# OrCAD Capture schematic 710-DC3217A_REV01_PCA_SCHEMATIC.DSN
size B
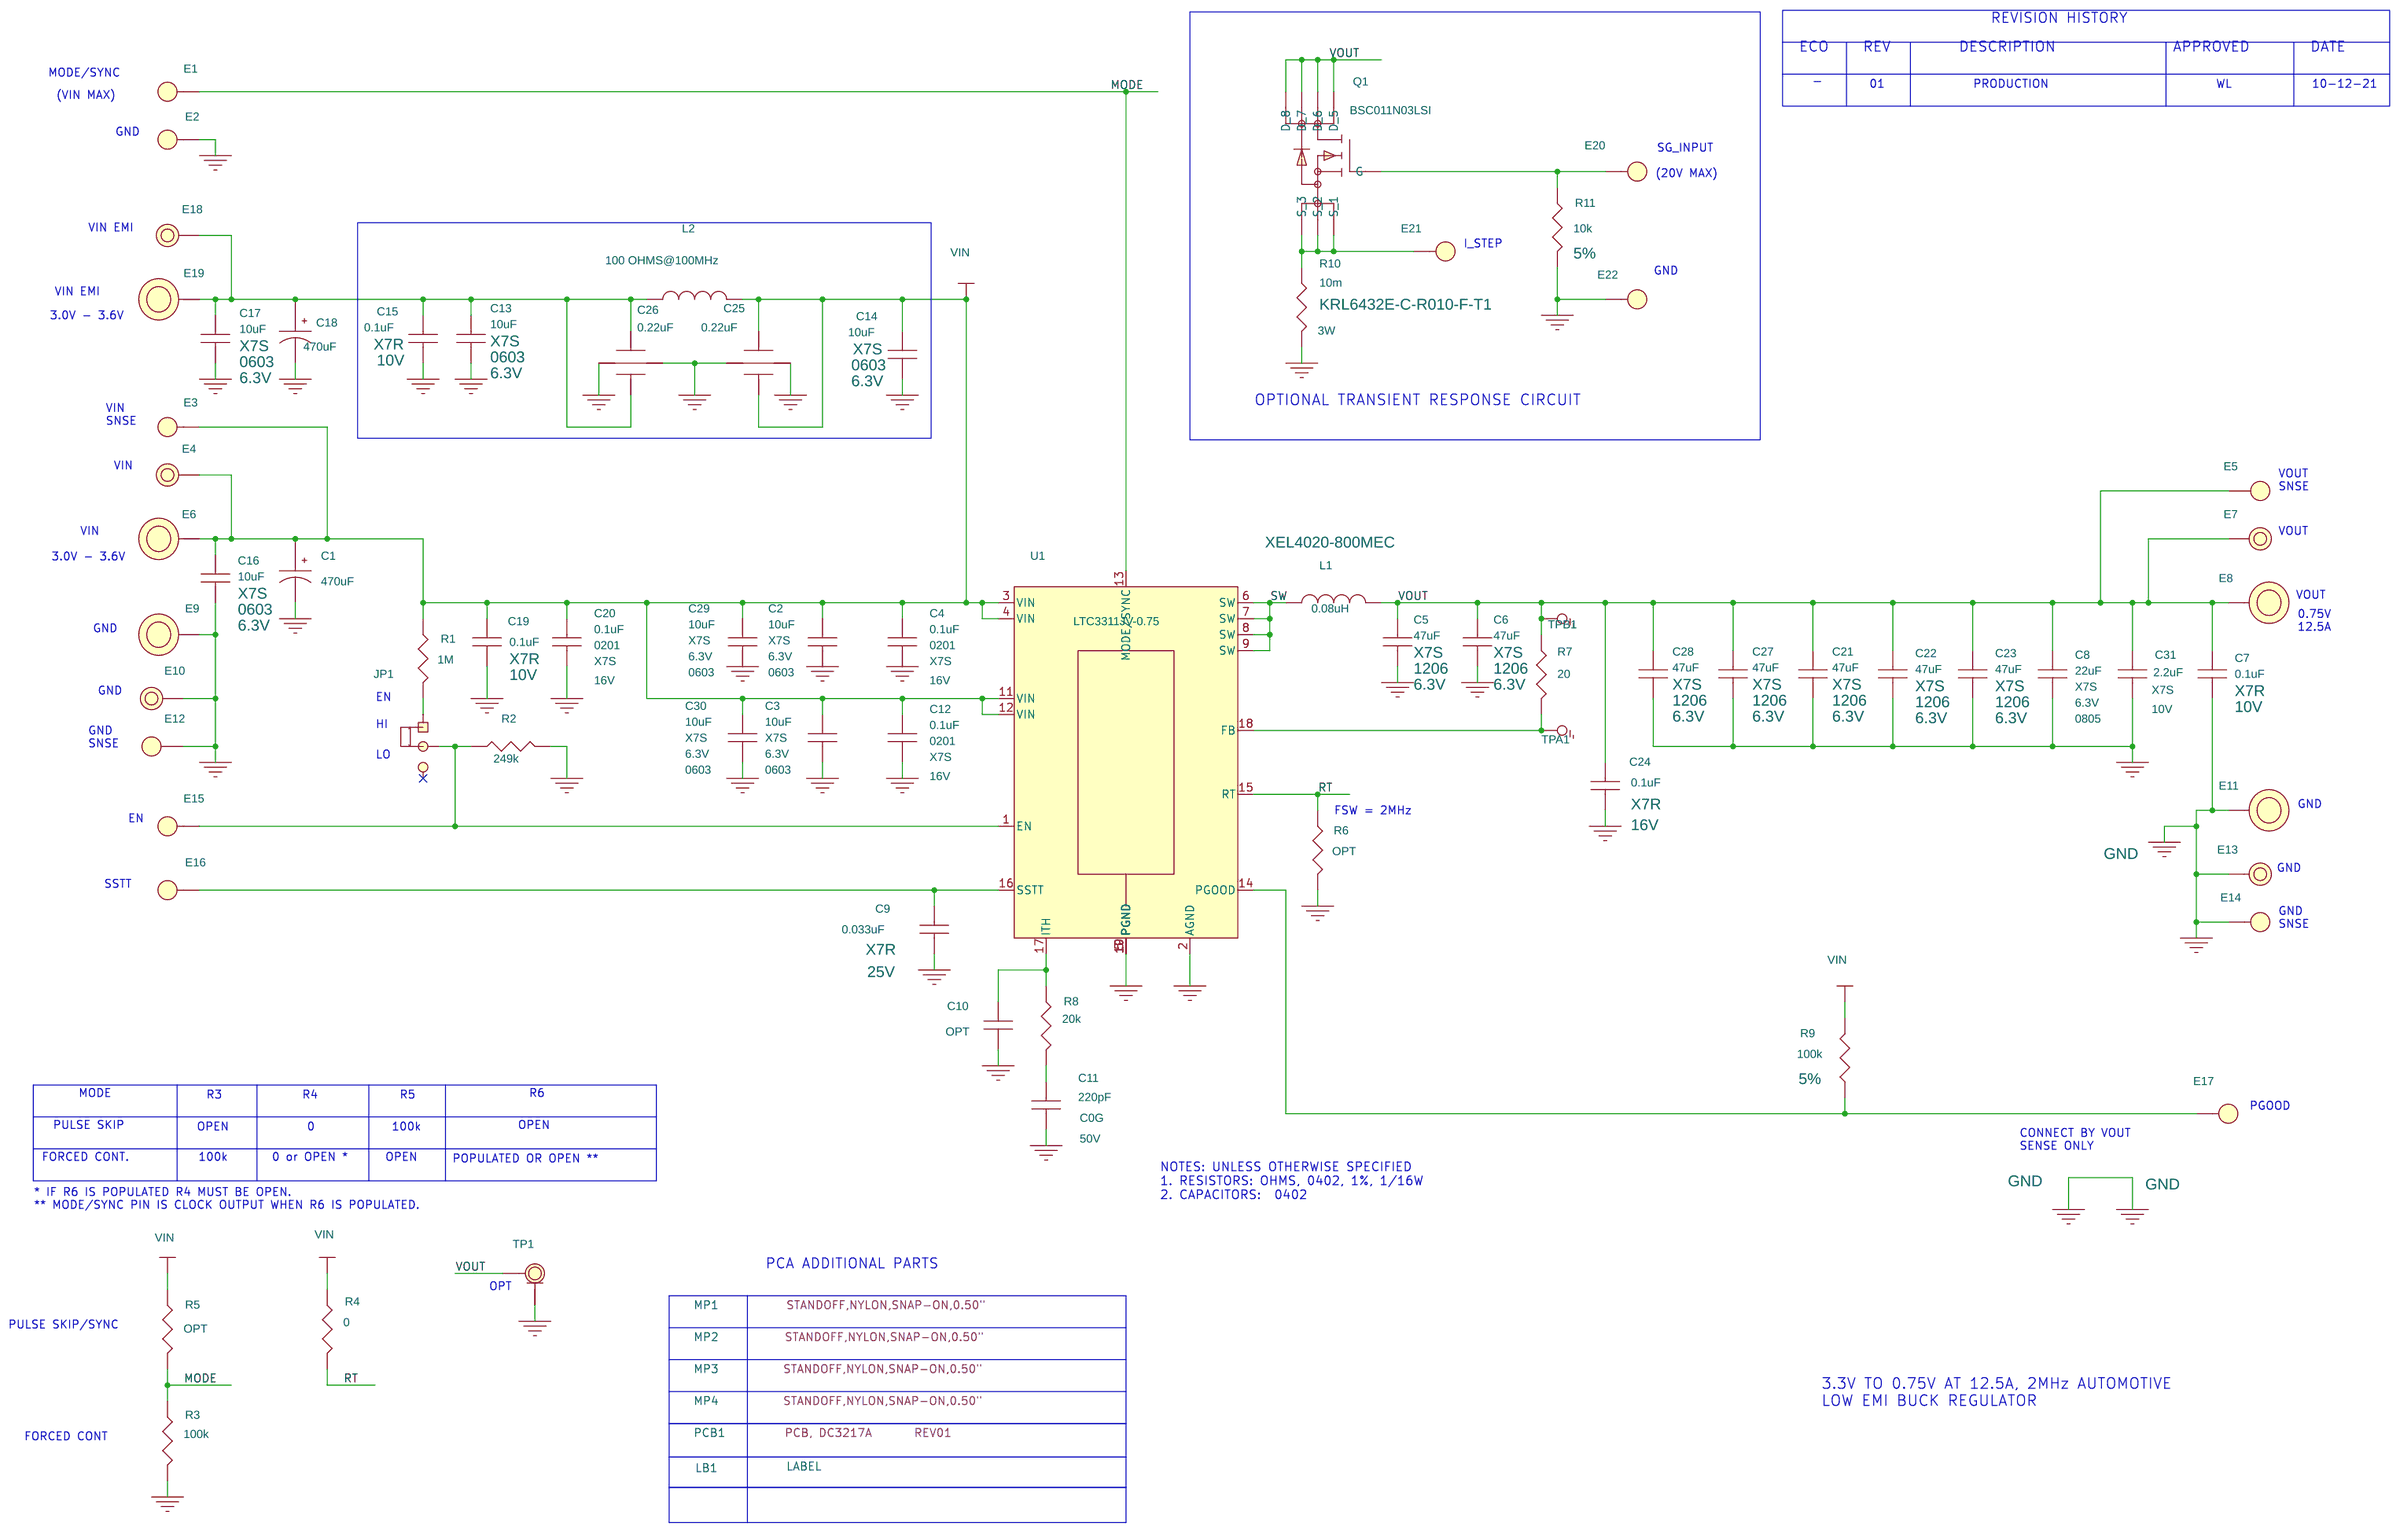
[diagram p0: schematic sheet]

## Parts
C1  470uF  [CAPMP7343N]
C2  10uF  [CC0603N]
C3  10uF  [CC0603N]
C4  0.1uF  [CC0201M]
C5  47uF  [CC1206N]
C6  47uF  [CC1206N]
C7  0.1uF  [CC0402N]
C8  22uF  [CC0805N]
C9  0.033uF  [CC0402N]
C10  OPT  [CC0402N]
C11  220pF  [CC0402N]
C12  0.1uF  [CC0201M]
C13  10uF  [CC0603N]
C14  10uF  [CC0603N]
C15  0.1uF  [CC0402N]
C16  10uF  [CC0603N]
C17  10uF  [CC0603N]
C18  470uF  [CAPMP7343N]
C19  0.1uF  [CC0402N]
C20  0.1uF  [CC0201M]
C21  47uF  [CC1206N]
C22  47uF  [CC1206N]
C23  47uF  [CC1206N]
C24  0.1uF  [CC0402N]
C25  0.22uF  [JOHANSON-X2Y-X14]
C26  0.22uF  [JOHANSON-X2Y-X14]
C27  47uF  [CC1206N]
C28  47uF  [CC1206N]
C29  10uF  [CC0603N]
C30  10uF  [CC0603N]
C31  2.2uF  [CC0402N]
E1  TEST POINT  [MILLMAX2308]
E2  TEST POINT  [MILLMAX2308]
E3  TEST POINT  [MILLMAX2308]
E4  TEST POINT  [MILLMAX2501]
E5  TEST POINT  [MILLMAX2308]
E6  BANANA JACK  [KEY-575-4]
E7  TEST POINT  [MILLMAX2501]
E8  BANANA JACK  [KEY-575-4]
E9  BANANA JACK  [KEY-575-4]
E10  TEST POINT  [MILLMAX2501]
E11  BANANA JACK  [KEY-575-4]
E12  TEST POINT  [MILLMAX2308]
E13  TEST POINT  [MILLMAX2501]
E14  TEST POINT  [MILLMAX2308]
E15  TEST POINT  [MILLMAX2308]
E16  TEST POINT  [MILLMAX2308]
E17  TEST POINT  [MILLMAX2308]
E18  TEST POINT  [MILLMAX2501]
E19  BANANA JACK  [KEY-575-4]
E20  TEST POINT  [MILLMAX2308]
E21  TEST POINT  [MILLMAX2308]
E22  TEST POINT  [MILLMAX2308]
JP1  HDR  [HD1X3-079]
L1  0.08uH  [COILCRAFT-XEL4020]
L2  100 OHMS@100MHz  [WURTH-74279226101]
LB1  LABEL  [895-0154_REV01]
MP1  STANDOFF  [KEYSTONE_8829-8834]
MP2  STANDOFF  [KEYSTONE_8829-8834]
MP3  STANDOFF  [KEYSTONE_8829-8834]
MP4  STANDOFF  [KEYSTONE_8829-8834]
PCB1  PCB, DC3217A
Q1  BSC011N03LSI  [INFINEON-PG-TDSON-8]
R1  1M  [CR0402N]
R2  249k  [CR0402N]
R3  100k  [CR0402N]
R4  0  [CR0402N]
R5  OPT  [CR0402N]
R6  OPT  [CR0402N]
R7  20  [CR0402N]
R8  20k  [CR0402N]
R9  100k  [CR0402N]
R10  10m  [SUSUMU-KRL6432]
R11  10k  [CR0402N]
TP1  U.FL  [HIROSE-FL-R-SMT-1]
TPA1  COPPER FEATURE PAD  [PADSTYLE1]
TPB1  COPPER FEATURE PAD  [PADSTYLE1]
U1  LTC3311JV-0.75  [LTC-LQFN-18-1548]
XJP1  SHUNT  [SAMTEC-SHUNT-079]

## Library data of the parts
C1 C18 = CAP_P_ALT: CAP.,470uF,TANT,POSCAP,6.3V,20%,7343,10mOHMS,TCF; CLASS: DISCRETE; Dielectric Type: TANT,POSCAP; FPLIST: CAPMP7343N,CAPMP7343L,CAPMP7343M; Inventory Qty: 4200; Manufacturer: PANASONIC; Manufacturer PN: 6TCF470MAH; PART_NUMBER: 150-0550; Package Size: 7343; Rated Voltage: 6.3V; Tolerance: 20%
C2 C3 C13 C14 C16 C17 C29 C30 = CAP: CAP.,10uF,X7S,6.3V,20%,0603; CLASS: DISCRETE; Dielectric Type: X7S; FPLIST: CC0603N,CC0603L,CC0603M; Inventory Qty: 34800; Manufacturer: TDK; Manufacturer PN: C1608X7S0J106M080AC; PART_NUMBER: 150-1745; Package Size: 0603; Rated Voltage: 6.3V; Tolerance: 20%
C4 C12 C20 = CAP: CAP.,0.1uF,X7S,16V,10%,0201; CLASS: DISCRETE; Dielectric Type: X7S; FPLIST: CC0201N,CC0201L,CC0201M; Inventory Qty: 73200; Manufacturer: MURATA; Manufacturer PN: GRM033C71C104KE14D; PART_NUMBER: 150-0807; Package Size: 0201; Rated Voltage: 16V; Temperature Coefficient: X7S; Tolerance: 10%
C5 C6 C21-C23 C27 C28 = CAP: CAP.,47uF,X7S,6.3V,20%,1206; CLASS: DISCRETE; Dielectric Type: X7S; FPLIST: CC1206N,CC1206L,CC1206M; Inventory Qty: 7200; Manufacturer: TDK; Manufacturer PN: C3216X7S0J476M160AC; PART_NUMBER: 150-2602; Package Size: 1206; Rated Voltage: 6.3V; Tolerance: 20%
C7 C15 C19 = CAP: CAP.,0.1uF,X7R,10V,10%,0402,AEC-Q200; CLASS: DISCRETE; Dielectric Type: X7R; FPLIST: CC0402N,CC0402L,CC0402M; Inventory Qty: 59100; Manufacturer: MURATA; Manufacturer PN: GCM155R71A104KA55D; PART_NUMBER: 150-1790; Package Size: 0402; Rated Voltage: 10V; Temperature Coefficient: X7R; Tolerance: 10%
C8 = CAP: CAP.,22uF,X7S,6.3V,20%,0805; CLASS: DISCRETE; Dielectric Type: X7S; FPLIST: CC0805N,CC0805L,CC0805M; Inventory Qty: 12300; Manufacturer: TDK; Manufacturer PN: C2012X7S0J226M125AC; PART_NUMBER: 150-0806; Package Size: 0805; Rated Voltage: 6.3V; Temperature Coefficient: X7S; Tolerance: 20%
C9 = CAP: CAP.,0.033uF,X7R,25V,10%,0402; CLASS: DISCRETE; Dielectric Type: X7R; FPLIST: CC0402N,CC0402L,CC0402M; Inventory Qty: 27937; Manufacturer: KEMET; Manufacturer PN: C0402C333K3RACTU; PART_NUMBER: 150-0484; Package Size: 0402; Rated Voltage: 25V; Tolerance: 10%
C10 = CAP: CAP., OPTION, 0402; CLASS: DISCRETE; FPLIST: CC0402N,CC0402L,CC0402M; PART_NUMBER: 150-3148; Package Size: 0402; Package Type: SMD
C11 = CAP: CAP.,220pF,C0G,50V,5%,0402; CLASS: DISCRETE; Dielectric Type: C0G; FPLIST: CC0402N,CC0402L,CC0402M; Inventory Qty: 29935; Manufacturer: AVX; Manufacturer PN: 04025A221JAT2A; PART_NUMBER: 150-2013; Package Size: 0402; Rated Voltage: 50V; Tolerance: 5%
C24 = CAP: CAP.,0.1uF,X7R,16V,10%,0402,AEC-Q200; CLASS: DISCRETE; Dielectric Type: X7R; Inventory Qty: 0; Manufacturer: MURATA; Manufacturer PN: GCM155R71C104KA55D; PART_NUMBER: 150-1882; Package Size: 0402; Package Type: Surface Mount, MLCC; Rated Voltage: 16V; Temperature Coefficient: X7R; Tolerance: 10%
C25 C26 = JOHANSON-X2Y: CAP.,0.22uF,X7R,6.3V,20%,0603; CLASS: DISCRETE; Dielectric Type: X7R; Inventory Qty: 12000; Manufacturer: JOHANSON DIELECTRICS; Manufacturer PN: 6R3X14W224MV4T; PART_NUMBER: 150-0876; Package Size: 0603; Rated Voltage: 6.3V; Temperature Coefficient: X7R; Tolerance: 20%
C31 = CAP: CAP.,2.2uf,X7S,10V,10%,0402,AEC-Q200; CLASS: DISCRETE; Dielectric Type: X7S; FPLIST: CC0402N,CC0402L,CC0402M; Inventory Qty: 0; Manufacturer: MURATA; Manufacturer PN: GRT155C71A225KE13D; PART_NUMBER: 150-1884; Package Size: 0402; Package Type: Surface Mount, MLCC; Rated Voltage: 10V; Temperature Coefficient: X7S; Tolerance: 10%
E1-E3 E5 E12 E14-E17 E20-E22 = TEST_POINT_.156_MILL-MAX_2308: TEST POINT,TURRET,0.064" MTG. HOLE,PCB 0.062" THK; CLASS: IO; Inventory Qty: 1142083; Manufacturer PN: 2308-2-00-80-00-00-07-0; PART_NUMBER: 260-0004
E4 E7 E10 E13 E18 = TESTPOINT_.219_MILL-MAX_2501: TEST POINT,TURRET,0.094" MTG. HOLE,PCB 0.062" THK; CLASS: IO; Inventory Qty: 823526; Manufacturer: MILL-MAX; Manufacturer PN: 2501-2-00-80-00-00-07-0; PART_NUMBER: 260-0003
E6 E8 E9 E11 E19 = BANANA_KEYSTONE-575-4: CONN.,BANANA JACK,FEMALE,THT,NON-INSULATED,SWAGE,0.218"; CLASS: IO; Inventory Qty: 203061; Manufacturer: KEYSTONE; Manufacturer PN: 575-4; PART_NUMBER: 250-0428
JP1 = 3_PIN_HEADER_.079_SINGLE_ROW_D: CONN.,HDR,MALE,1x3,2mm,VERT,ST,THT; CLASS: IO; Inventory Qty: 22026; Manufacturer: Wurth Elektronik; Manufacturer PN: 62000311121; PART_NUMBER: 250-0484
L1 = IND_ALT: IND.,0.08uH,PWR,20%,21.4A,1.8mOHMS,4x4mm,AEC-Q200; CLASS: DISCRETE; Inventory Qty: 0; Manufacturer: COILCRAFT; Manufacturer PN: XEL4020-800MEC; PART_NUMBER: 200-0900; Package Size: 4x4mm; Tolerance: 20%
L2 = IND_ALT: IND.,100 OHMS@100MHz,FERRITE BEAD,25%,8A,6mOHMS,1812; CLASS: DISCRETE; Inventory Qty: 3043; Manufacturer: WURTH ELEKTRONIK; Manufacturer PN: 74279226101; PART_NUMBER: 200-0280; Package Size: 1812; Tolerance: 25%
LB1 = BLANK_LABEL: LABEL SPEC, DEMO BOARD SERIAL NUMBER; Inventory Qty: 0; Manufacturer: BRADY; Manufacturer PN: THT-96-717-10; PART_NUMBER: 895-0154
MP1-MP4 = BLANK_MECHANICAL_PART: STANDOFF,NYLON,SNAP-ON,0.50"; CLASS: DISCRETE; FPLIST: KEYSTONE_8829-8834,MTG-8831; Inventory Qty: 214842; Manufacturer: KEYSTONE; Manufacturer PN: 8833; PART_NUMBER: 763-0007
PCB1 = BLANK_PCB_PART: BOM Notes: REV01; CLASS: DISCRETE; Inventory Qty: 0; Manufacturer: ADI APPROVED SUPPLIER; Manufacturer PN: 600-DC3217A; PART_NUMBER: 600-DC3217A
Q1 = 8P_N-CH_TYPE1A: XSTR.,MOSFET,N-CH,30V,37A,PG-TDSON-8; CLASS: DISCRETE; Inventory Qty: 1720; Manufacturer: INFINEON; PART_NUMBER: 240-0041; Package Type: PG-TDSON-8; Rated Voltage: 30V
R1 = RES: RES.,1M OHM,1%,1/16W,0402,AEC-Q200; CLASS: DISCRETE; FPLIST: CR0402N,CR0402L,CR0402M; Inventory Qty: 86432; Manufacturer: STACKPOLE ELECTRONICS, INC.; Manufacturer PN: RMCF0402FT1M00; PART_NUMBER: 100-2457; Package Size: 0402; Rated Power: 1/16W; Temperature Coefficient: 100ppm; Tolerance: 1%
R2 = RES: RES.,249k OHMS,1%,1/16W,0402,AEC-Q200; CLASS: DISCRETE; FPLIST: CR0402N,CR0402L,CR0402M; Inventory Qty: 26713; Manufacturer: NIC; Manufacturer PN: NRC04F2493TRF; PART_NUMBER: 100-2663; Package Size: 0402; Rated Power: 1/16W; Temperature Coefficient: 100ppm; Tolerance: 1%
R3 R9 = RES: RES.,100k OHMS,5%,1/16W,0402,AEC-Q200; CLASS: DISCRETE; FPLIST: CR0402N,CR0402L,CR0402M; Inventory Qty: 59032; Manufacturer: NIC; Manufacturer PN: NRC04J104TRF; PART_NUMBER: 100-0359; Package Size: 0402; Rated Power: 1/16W; Temperature Coefficient: 200ppm/C; Tolerance: 5%
R4 = RES: RES.,0 OHM,1/16W,0402,AEC-Q200; CLASS: DISCRETE; FPLIST: CR0402N,CR0402L,CR0402M; Inventory Qty: 127940; Manufacturer: NIC; Manufacturer PN: NRC04ZOTRF; PART_NUMBER: 100-2023; Package Size: 0402; Rated Power: 1/16W
R5 R6 = RES: RES., OPTION, 0402; CLASS: DISCRETE; FPLIST: CR0402N,CR0402L,CR0402M; PART_NUMBER: 100-0357; Package Size: 0402
R7 = RES: RES.,20 OHMS,1%,1/16W,0402,AEC-Q200; CLASS: DISCRETE; FPLIST: CR0402N,CR0402L,CR0402M; Inventory Qty: 29845; Manufacturer: NIC; Manufacturer PN: NRC04F20R0TRF; PART_NUMBER: 100-0250; Package Size: 0402; Rated Power: 1/16W; Temperature Coefficient: 100ppm; Tolerance: 1%
R8 = RES: RES.,20k OHMS,1%,1/16W,0402,AEC-Q200; CLASS: DISCRETE; FPLIST: CR0402N,CR0402L,CR0402M; Inventory Qty: 11520; Manufacturer: NIC; Manufacturer PN: NRC04F2002TRF; PART_NUMBER: 100-2549; Package Size: 0402; Rated Power: 1/16W; Temperature Coefficient: 100ppm/C; Tolerance: 1%
R10 = RES: RES.,10m OHMS,1%,3W,6.3 X3.1mm,AEC-Q200 LONG-SIDE TERM; CLASS: DISCRETE; FPLIST: SUSUMU-KRL6432,SUSUMU-KRL6432-4PIN; Inventory Qty: 0; Manufacturer: SUSUMU; Manufacturer PN: KRL6432E-C-R010-F-T1; PART_NUMBER: 100-1792; Package Size: 6.3 X3.1mm; Rated Power: 3W; Temperature Coefficient: 50PPM; Tolerance: 1%
R11 = RES: RES.,10k OHMS,5%,1/16W,0402,AEC-Q200; CLASS: DISCRETE; Inventory Qty: 64117; Manufacturer: NIC; Manufacturer PN: NRC04J103TRF; PART_NUMBER: 100-0214; Package Size: 0402; Rated Power: 1/16W; Temperature Coefficient: 200ppm; Tolerance: 5%
TP1 = HIROSE-U.FL-R-SMT-1: CONN.,U.FL,RECEPT,ST SMD,0Hz to 6GHz 50Ohm; CLASS: IO; Inventory Qty: 0; Manufacturer: HIROSE ELECTRIC; Manufacturer PN: U.FL-R-SMT-1(10); PART_NUMBER: 250-0939
TPA1 TPB1 = PAD_SMALL_FILLED: TESTPOINT, PCB COPPER FEATURE; CLASS: IO; Manufacturer: N/A; Manufacturer PN: N/A; PART_NUMBER: PCBPADS-11
U1 = LTC3311JV-XXXX: IC,Low Voltage Synch Stepdown Reg,LQFN-18,PRELIM-PART NOT FOR PRODUCTION; CLASS: IC; Inventory Qty: 0; Manufacturer: ANALOG DEVICES; Manufacturer PN: LTC3311JV-0.75#PBF; PART_NUMBER: LTC3311JV-0.75#PBF; Package Size: 18-LQFN; Package Type: LQFN-18
XJP1 = CONN_SHUNT_2_POS_2mm: CONN.,SHUNT,FEMALE,2-POS,2mm; CLASS: MECHANICAL; Inventory Qty: 268916; Manufacturer: SAMTEC; Manufacturer PN: 2SN-BK-G; PART_NUMBER: 250-0419

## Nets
GND: C1.2 C2.2 C3.2 C4.2 C5.2 C6.2 C7.2 C8.2 C9.2 C10.2 C11.2 C12.2 C13.2 C14.2 C15.2 C16.2 C17.2 C18.2 C19.2 C20.2 C21.2 C22.2 C23.2 C24.2 C25.3(G1) C25.4(G2) C26.3(G1) C26.4(G2) C27.2 C28.2 C29.2 C30.2 C31.2 E2.1(A) E9.1 E10.1 E11.1 E12.1(A) E13.1 E14.1(A) E22.1(A) R2.2 R3.2 R6.2 R10.2 R11.2 TP1.2(GND) TP1.3(GND) TP1.4(GND) TP1.5(GND) U1.2(AGND) U1.5(PGND) U1.10(PGND) U1.19(PGND)
VIN: C1.1 C2.1 C3.1 C4.1 C12.1 C14.1 C16.1 C19.1 C20.1 C25.1(A) C25.2(B) C29.1 C30.1 E3.1(A) E4.1 E6.1 L2.2 R1.1 R4.1 R5.1 R9.1 U1.3(VIN) U1.4(VIN) U1.11(VIN) U1.12(VIN)
MODE: E1.1(A) R3.1 R5.2 U1.13(MODE/SYNC)
RT: R4.2 R6.1 U1.15(RT)
SW: L1.1 U1.6(SW) U1.7(SW) U1.8(SW) U1.9(SW)
VOUT: C5.1 C6.1 C7.1 C8.1 C21.1 C22.1 C23.1 C24.1 C27.1 C28.1 C31.1 E5.1(A) E7.1 E8.1 L1.2 Q1.5(D) Q1.6(D) Q1.7(D) Q1.8(D) R7.1 TP1.1 TPB1.1
N16777546: E15.1(A) JP1.2 R2.1 U1.1(EN)
N16777572: R7.2 TPA1.1 U1.18(FB)
N16777640: E17.1(A) R9.2 U1.14(PGOOD)
N16777648: C10.1 R8.1 U1.17(ITH)
N16777650: C11.1 R8.2
N16777742: JP1.1 R1.2
N16777770: C9.1 E16.1(A) U1.16(SSTT)
N16814255: C13.1 C15.1 C17.1 C18.1 C26.1(A) C26.2(B) E18.1 E19.1 L2.1
N16841248: E20.1(A) Q1.4(G) R11.1
N16841304: E21.1(A) Q1.1(S) Q1.2(S) Q1.3(S) R10.1

Not connected (* = marked no-connect by the designer): JP1 3*

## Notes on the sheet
- REVISION HISTORY
- ECO
- REV
- DESCRIPTION
- APPROVED
- DATE
- MODE/SYNC
- -
- (VIN MAX)
- 01
- PRODUCTION
- WL
- 10-12-21
- GND
- SG_INPUT
- (20V MAX)
- VIN EMI
- I_STEP
- GND
- VIN EMI
- 3.0V - 3.6V
- OPTIONAL TRANSIENT RESPONSE CIRCUIT
- VIN
  SNSE
- VIN
- VOUT
  SNSE
- VIN
- VOUT
- 3.0V - 3.6V
- VOUT
- GND
- 0.75V
  12.5A
- GND
- EN
- GND
  SNSE
- HI
- LO
- FSW = 2MHz
- GND
- EN
- GND
- SSTT
- GND
  SNSE
- MODE
- R3
- R4
- R5
- R6
- PGOOD
- PULSE SKIP
- OPEN
- 0
- 100k
- OPEN
- CONNECT BY VOUT
  SENSE ONLY
- FORCED CONT.
- 100k
- 0 or OPEN *
- OPEN
- POPULATED OR OPEN **
- NOTES: UNLESS OTHERWISE SPECIFIED
  1. RESISTORS: OHMS, 0402, 1%, 1/16W
  2. CAPACITORS:  0402
- * IF R6 IS POPULATED R4 MUST BE OPEN.
  ** MODE/SYNC PIN IS CLOCK OUTPUT WHEN R6 IS POPULATED.
- PCA ADDITIONAL PARTS
- OPT
- PULSE SKIP/SYNC
- 3.3V TO 0.75V AT 12.5A, 2MHz AUTOMOTIVE
  LOW EMI BUCK REGULATOR
- FORCED CONT
